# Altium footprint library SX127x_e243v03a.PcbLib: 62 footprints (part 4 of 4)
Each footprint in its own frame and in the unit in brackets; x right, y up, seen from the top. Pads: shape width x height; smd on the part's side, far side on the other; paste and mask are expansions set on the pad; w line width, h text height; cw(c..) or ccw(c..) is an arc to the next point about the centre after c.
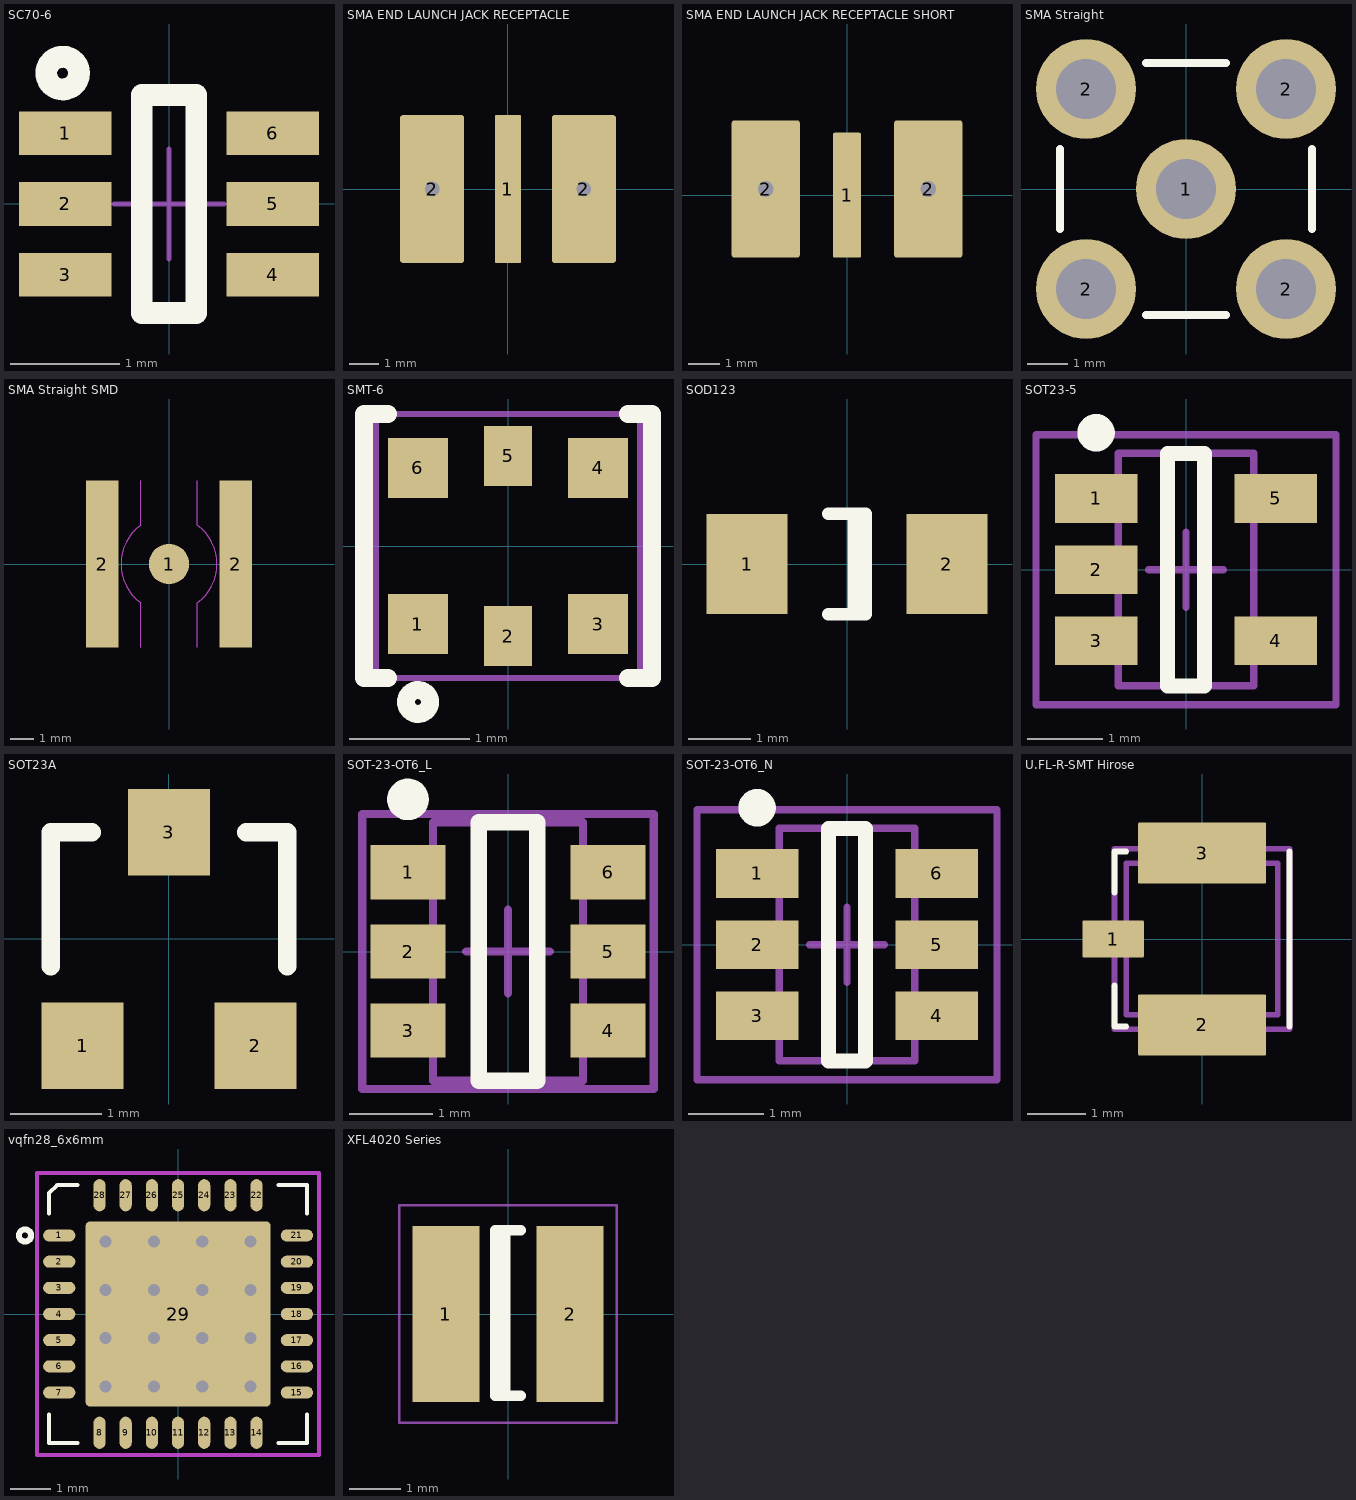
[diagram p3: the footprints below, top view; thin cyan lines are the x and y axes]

## SC70-6 [mm] "SC70 6-Leads, Body 2.0x1.25mm, Pitch 0.65mm"
height 1.45
pads (6):
  rect 0.85x0.4 smd mask+0.05: 1(-0.95,0.65) 2(-0.95,0) 3(-0.95,-0.65) 4(0.95,-0.65) 5(0.95,0) 6(0.95,0.65)
Top Overlay:
  circle w0.2: c-0.975,1.2 r0.15
  lines w0.2: -0.25,-1 -0.25,1 0.25,1 0.25,-1 -0.25,-1
Mechanical 15:
  lines w0.05: -0.5,0 0.5,0 ; 0,-0.5 0,0.5
3D body: height 1.45, standoff 0, extent -0.625,-1 0.625,1

## SMA END LAUNCH JACK RECEPTACLE [mm] "SMA Connector - End Launch Jack Receptacle"
height 8
pads (3):
  rrect10% 0.9x5.08 smd paste+0 mask+0.05: 1(0,0)
  rrect10% 2.2x5.08 hole 0.5 mask+0.05: 2(-2.6,0) 2(2.6,0)

## SMA END LAUNCH JACK RECEPTACLE SHORT [mm] "SMA Connector - End Launch Jack Receptacle - Short"
height 8
pads (3):
  rrect10% 0.9x4 smd paste+0 mask+0.05: 1(0,0)
  rrect10% 2.2x4.4 hole 0.5 mask+0.05: 2(-2.6,0.2) 2(2.6,0.2)

## SMA Straight [mm] "SMA Connector; Straight"
height 10
pads (5):
  round 2.5 hole 1.5 paste+0 mask+0.1: 1(0,0) 2(-2.5,-2.5) 2(-2.5,2.5) 2(2.5,-2.5) 2(2.5,2.5)
Top Overlay:
  lines w0.2: -3.15,-1 -3.15,1 ; -1,-3.15 1,-3.15 ; -1,3.15 1,3.15 ; 3.15,-1 3.15,1
Mechanical 1:
  circle w0.025: c0,0 r0.2

## SMA Straight SMD [mm] "SMA Connector; Straight; SMD"
height 10
pads (3):
  round 1.73 smd paste+0 mask+0.05: 1(0,0)
  rect 1.4x7.12 smd paste+0 mask+0.05: 2(-2.85,0) 2(2.85,0)
Top Paste:
  region: -1.24,3.56 -1.24,1.71 -2.24,1.71 -2.24,3.56
  region: 2.25,3.56 2.25,1.71 1.25,1.71 1.25,3.56
  region: 2.25,-1.7 2.25,-3.55 1.25,-3.55 1.25,-1.7
  region: -1.25,-1.7 -1.25,-3.55 -2.25,-3.55 -2.25,-1.7
Top Solder:
  region: -1.21,-4 -3.8,-4 -3.8,-3.55 -1.21,-3.55
  region: -3.5,4 -3.9,4 -3.9,-4 -3.5,-4
  region: -3.8,3.55 -3.8,4 -1.2,4 -1.2,3.55
  region: -2.13,-3.61 -1.21,-3.61 -1.21,-1.66 -2.13,-0.8
  region: -2.12,3.61 -1.2,3.61 -1.2,1.66 -2.12,0.8
  region: 2.13,3.61 1.21,3.61 1.21,1.66 2.13,0.8
  region: 2.13,-3.61 1.21,-3.61 1.21,-1.66 2.13,-0.8
  region: 3.8,-4 1.21,-4 1.21,-3.55 3.8,-3.55
  region: 3.9,4 3.5,4 3.5,-4 3.9,-4
  region: 1.21,3.55 1.21,4 3.8,4 3.8,3.55
Mechanical 12 keep-out:
  lines w0.05: -1.212,-1.653 cw(c0,0) -1.208,1.657 ; -1.21,-3.565 -1.21,-1.66 ; -1.2,1.66 -1.2,3.565 ; 1.208,-3.558 1.208,-1.657 ccw(c0,0) 1.212,1.653 ; 1.21,1.66 1.21,3.56

## SMT-6 [mm] "SMT-6 Package"
height 1.25
pads (6):
  rect 0.5x0.5 smd mask+0.05: 1(-0.75,-0.65) 3(0.75,-0.65) 4(0.75,0.65) 6(-0.75,0.65)
  rect 0.4x0.5 smd mask+0.05: 2(0,-0.75) 5(0,0.75)
Top Overlay:
  circle w0.15: c-0.75,-1.3 r0.1
  lines w0.15: -1,-1.1 -1.2,-1.1 -1.2,1.1 -1,1.1 ; 1,-1.1 1.2,-1.1 1.2,1.1 1,1.1
Mechanical 15:
  lines w0.05: -1.1,-1.1 -1.1,1.1 1.1,1.1 1.1,-1.1 -1.1,-1.1
3D body: height 1, standoff 0, extent -0.85,-0.85 0.85,0.85

## SOD123 [mm] "SOD123; Chip Diode; Body  2.7 x 1.6 mm (LxW typ)"
height 1.35
pads (2):
  rect 1.3x1.6 smd mask+0.05: 1(-1.6,0) 2(1.6,0)
Top Overlay:
  lines w0.2: -0.3,-0.8 0.3,-0.8 0.3,0.8 -0.3,0.8 ; 0.11,-0.8 0.11,0.8

## SOT23-5 [mm] "SOT23, 5-Leads, Body 2.9x1.6mm, Pitch 0.95mm, Lead Span 2.8mm, IPC Medium Density"
height 1.45
pads (5):
  rect 1.1x0.65 smd mask+0.05: 1(-1.2,0.95) 2(-1.2,0) 3(-1.2,-0.95) 4(1.2,-0.95) 5(1.2,0.95)
Top Overlay:
  circle w0.25: c-1.2,1.825 r0.125
  lines w0.2: -0.25,-1.55 -0.25,1.55 0.25,1.55 0.25,-1.55 -0.25,-1.55
Mechanical 13:
  lines w0.1: -0.9,-1.55 0.9,-1.55 0.9,1.55 -0.9,1.55 -0.9,-1.55
Mechanical 15:
  lines w0.1: -0.5,0 0.5,0 ; 0,-0.5 0,0.5 ; -2,-1.8 2,-1.8 2,1.8 -2,1.8 -2,-1.8
3D body: height 1.45, standoff 0, extent -0.9,-1.55 0.9,1.55

## SOT23A [mm] "SOT-23; 3 Leads; Body 3.0 x 2.5 mm, inc. leads (LxW max)"
height 1.2
pads (3):
  rect 0.9x0.95 smd: 1(-0.95,-1.175) 2(0.95,-1.175) 3(0,1.175)
Top Overlay:
  lines w0.2: -1.3,-0.3 -1.3,1.175 -0.85,1.175 ; 0.85,1.175 1.3,1.175 1.3,-0.3

## SOT-23-OT6_L [mm] "SOT23, 6-Leads, Body 2.9x1.6mm, Pitch 0.95mm, Lead Span 2.7mm, IPC High Density"
height 1.45
pads (6):
  rect 0.9x0.65 smd: 1(-1.2,0.95) 2(-1.2,0) 3(-1.2,-0.95) 4(1.2,-0.95) 5(1.2,0) 6(1.2,0.95)
Top Overlay:
  circle w0.25: c-1.2,1.825 r0.125
  lines w0.2: -0.35,-1.55 0.35,-1.55 0.35,1.55 -0.35,1.55 -0.35,-1.55
Mechanical 13:
  lines w0.1: -0.9,-1.55 -0.9,1.55 0.9,1.55 0.9,-1.55 -0.9,-1.55
Mechanical 15:
  lines w0.1: -0.5,0 0.5,0 ; 0,-0.5 0,0.5 ; -1.75,-1.65 -1.75,1.65 1.75,1.65 1.75,-1.65 -1.75,-1.65
3D body: height 1.45, standoff 0, extent -0.9,-1.55 0.9,1.55

## SOT-23-OT6_N [mm] "SOT23, 6-Leads, Body 2.9x1.6mm, Pitch 0.95mm, Lead Span 2.7mm, IPC Medium Density"
height 1.45
pads (6):
  rect 1.1x0.65 smd: 1(-1.2,0.95) 2(-1.2,0) 3(-1.2,-0.95) 4(1.2,-0.95) 5(1.2,0) 6(1.2,0.95)
Top Overlay:
  circle w0.25: c-1.2,1.825 r0.125
  lines w0.2: -0.25,-1.55 0.25,-1.55 0.25,1.55 -0.25,1.55 -0.25,-1.55
Mechanical 13:
  lines w0.1: -0.9,-1.55 -0.9,1.55 0.9,1.55 0.9,-1.55 -0.9,-1.55
Mechanical 15:
  lines w0.1: -0.5,0 0.5,0 ; 0,-0.5 0,0.5 ; -2,-1.8 -2,1.8 2,1.8 2,-1.8 -2,-1.8
3D body: height 1.45, standoff 0, extent -0.9,-1.55 0.9,1.55

## U.FL-R-SMT Hirose [mm] "Hirose U.FL RF receptacle - U.FL-R-SMT"
height 1.2
pads (3):
  rrect5% 1.05x0.635 smd: 1(-1.525,0)
  rrect5% 2.2x1.05 smd: 2(0,-1.475) 3(0,1.475)
Top Overlay:
  lines w0.1: -1.5,-0.8 -1.5,-1.5 -1.3,-1.5 ; -1.5,0.8 -1.5,1.5 -1.3,1.5 ; 1.5,-1.5 1.5,1.5
Mechanical 13:
  lines w0.1: -1.5,-1.55 1.5,-1.55 1.5,1.55 -1.5,1.55 -1.5,-1.55
Mechanical 15:
  lines w0.1: -1.3,-1.3 1.3,-1.3 1.3,1.3 -1.3,1.3 -1.3,-1.3
3D body: height 16, standoff 1.3, extent -1.5,-1.5 1.5,1.5

## vqfn28_6x6mm [mm] "28 Leads, Body 6.0x6.0mm, Pitch 0.65mm, VQFN28"
height 1
pads (29):
  oval 0.8x0.3 smd mask+0.05: 1(-2.95,1.95) 2(-2.95,1.3) 3(-2.95,0.65) 4(-2.95,0) 5(-2.95,-0.65) 6(-2.95,-1.3) 7(-2.95,-1.95) 15(2.95,-1.95) 16(2.95,-1.3) 17(2.95,-0.65) 18(2.95,0) 19(2.95,0.65) 20(2.95,1.3) 21(2.95,1.95)
  oval 0.3x0.8 smd mask+0.05: 8(-1.95,-2.95) 9(-1.3,-2.95) 10(-0.65,-2.95) 11(0,-2.95) 12(0.65,-2.95) 13(1.3,-2.95) 14(1.95,-2.95) 22(1.95,2.95) 23(1.3,2.95) 24(0.65,2.95) 25(0,2.95) 26(-0.65,2.95) 27(-1.3,2.95) 28(-1.95,2.95)
  rrect5% 4.6x4.6 smd paste-3.3 mask+0.05: 29(0,0)
via 0.6,-1.8 diameter 0.6 hole 0.3
via 1.8,-0.6 diameter 0.6 hole 0.3
via -1.8,1.8 diameter 0.6 hole 0.3
via -1.8,-0.6 diameter 0.6 hole 0.3
via -1.8,0.6 diameter 0.6 hole 0.3
via 0.6,-0.6 diameter 0.6 hole 0.3
via 1.8,-1.8 diameter 0.6 hole 0.3
via -0.6,-1.8 diameter 0.6 hole 0.3
via -1.8,-1.8 diameter 0.6 hole 0.3
via -0.6,1.8 diameter 0.6 hole 0.3
via -0.6,0.6 diameter 0.6 hole 0.3
via -0.6,-0.6 diameter 0.6 hole 0.3
via 0.6,0.6 diameter 0.6 hole 0.3
via 0.6,1.8 diameter 0.6 hole 0.3
via 1.8,1.8 diameter 0.6 hole 0.3
via 1.8,0.6 diameter 0.6 hole 0.3
Top Overlay:
  circle w0.15: c-3.8,1.95 r0.15
  lines w0.1: -3.2,-2.5 -3.2,-3.2 -2.5,-3.2 ; -3.2,2.5 -3.2,3 -3,3.2 -2.5,3.2 ; 2.5,-3.2 3.2,-3.2 3.2,-2.5 ; 2.5,3.2 3.2,3.2 3.2,2.5
Top Paste:
  region: -1.6,-0.8 -1.6,-1.6 -0.8,-1.6 -0.8,-0.8
  region: 0.8,-0.8 0.8,-1.6 1.6,-1.6 1.6,-0.8
  region: -0.4,-0.8 -0.4,-1.6 0.4,-1.6 0.4,-0.8
  region: 0.8,0.4 0.8,-0.4 1.6,-0.4 1.6,0.4
  region: -1.6,1.6 -1.6,0.8 -0.8,0.8 -0.8,1.6
  region: -0.4,1.6 -0.4,0.8 0.4,0.8 0.4,1.6
  region: -1.6,0.4 -1.6,-0.4 -0.8,-0.4 -0.8,0.4
  region: -0.4,0.4 -0.4,-0.4 0.4,-0.4 0.4,0.4
  region: 0.8,1.6 0.8,0.8 1.6,0.8 1.6,1.6
Mechanical 15 keep-out:
  lines w0.1: -3.5,-3.5 -3.5,3.5 3.5,3.5 3.5,-3.5 -3.5,-3.5
3D body: height 1, standoff 0.05, extent -3,-3 3,3

## XFL4020 Series [mm] "Chip SMD component ; Body 4.0 x 4.0 mm (LxW typ)"
height 2.1
pads (2):
  rect 1.3x3.4 smd mask+0.05: 1(-1.2,0) 2(1.2,0)
Top Overlay:
  lines w0.2: -0.056,-1.579 -0.056,1.621 ; 0.25,-1.579 -0.246,-1.579 -0.246,1.621 0.25,1.621
Mechanical 15:
  lines w0.05: -2.1,-2.1 2.1,-2.1 2.1,2.1 -2.1,2.1 -2.1,-2.1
